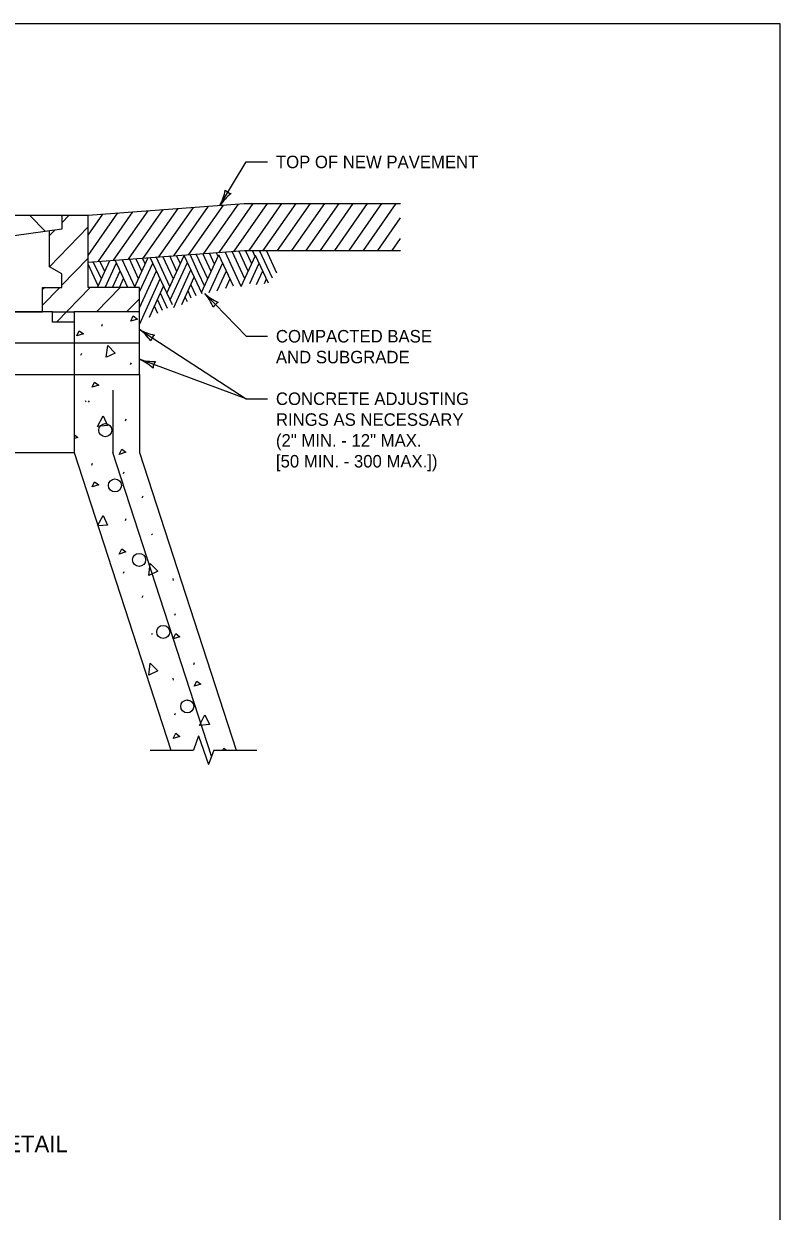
# Model space of a CAD drawing. Extents: x 49991.4 to 50021, y 49987.6 to 50011.4.
# Drawn here: x 50004.98 to 50008.61, y 50005.56 to 50011.26 of the extents above; entities that cross this region are included whole.
import ezdxf

# ---------------------------------------------------------------- set-up
doc = ezdxf.new("R2010")
doc.units = 0
for name, color, linetype in [('Level 1', 7, 'Continuous'), ('Level 2', 7, 'Continuous'), ('Level 3', 7, 'Continuous'), ('Level 4', 7, 'Continuous'), ('Level 6', 7, 'Continuous')]:
    doc.layers.add(name, color=color, linetype=linetype)

msp = doc.modelspace()

# ---------------------------------------------------------------- linework, layer by layer
at = {"layer": 'Level 1'}
for p, q in [((50005.2912, 50010.3439), (50006.0412, 50010.3995)), ((50005.4134, 50010.1279), (50005.5796, 50010.3653)), ((50005.4859, 50010.1333), (50005.6521, 50010.3707)), ((50005.5583, 50010.1387), (50005.7245, 50010.376)), ((50005.6306, 50010.144), (50005.797, 50010.3814)), ((50005.703, 50010.1494), (50005.8693, 50010.3868)), ((50005.7755, 50010.1548), (50005.9417, 50010.3921)), ((50005.848, 50010.1601), (50006.0142, 50010.3975)), ((50005.9204, 50010.1655), (50006.0842, 50010.3995)), ((50005.9928, 50010.1708), (50006.1529, 50010.3995)), ((50006.0412, 50010.3995), (50006.7912, 50010.3995)), ((50006.0641, 50010.1745), (50006.2216, 50010.3995)), ((50006.1327, 50010.1745), (50006.2902, 50010.3995)), ((50006.2014, 50010.1745), (50006.359, 50010.3995)), ((50006.2701, 50010.1745), (50006.4276, 50010.3995)), ((50006.3387, 50010.1745), (50006.4963, 50010.3995)), ((50006.4074, 50010.1745), (50006.5649, 50010.3995)), ((50006.476, 50010.1745), (50006.6336, 50010.3995)), ((50006.5447, 50010.1745), (50006.7023, 50010.3995)), ((50006.6134, 50010.1745), (50006.7709, 50010.3995)), ((50003.6589, 50010.3439), (50005.2912, 50010.3439)), ((50005.011, 50010.3439), (50005.0866, 50010.2656)), ((50005.161, 50010.3439), (50005.1661, 50010.3385)), ((50005.1661, 50010.3439), (50005.1661, 50010.2767)), ((50005.2012, 50010.3439), (50005.1661, 50010.3076)), ((50005.2912, 50010.1496), (50005.4347, 50010.3545)), ((50005.2912, 50010.2476), (50005.3622, 50010.3492)), ((50005.2912, 50009.9971), (50005.2912, 50010.3439)), ((50005.3411, 50010.1226), (50005.5071, 50010.3599)), ((50006.682, 50010.1745), (50006.7912, 50010.3304)), ((50005.1661, 50010.2767), (50004.4752, 50010.1795)), ((50005.2912, 50010.2875), (50005.107, 50010.0964)), ((50005.1316, 50010.2719), (50005.107, 50010.2464)), ((50005.107, 50010.0964), (50005.107, 50010.2684)), ((50006.7508, 50010.1745), (50006.7912, 50010.2323)), ((50005.2912, 50010.1375), (50005.1661, 50010.0076)), ((50005.2912, 50010.1189), (50006.0422, 50010.1745)), ((50005.5139, 50009.9971), (50005.5801, 50010.1403)), ((50005.5491, 50010.0749), (50005.5215, 50010.136)), ((50005.5661, 50010.11), (50005.5533, 50010.1383)), ((50005.6961, 50009.9141), (50005.5897, 50010.141)), ((50005.6848, 50010.0014), (50005.6189, 50010.1432)), ((50005.7012, 50010.0368), (50005.6511, 50010.1455)), ((50005.6701, 50009.9698), (50005.7533, 50010.1502)), ((50005.7183, 50010.0738), (50005.6843, 50010.148)), ((50005.7347, 50010.11), (50005.7162, 50010.1504)), ((50005.8385, 50009.9656), (50005.7533, 50010.1502)), ((50005.8238, 50010.0631), (50005.7816, 50010.1552)), ((50005.8661, 50010.0379), (50005.8102, 50010.1573)), ((50005.8356, 50009.972), (50005.9199, 50010.1542)), ((50005.8825, 50010.0734), (50005.843, 50010.1598)), ((50005.8991, 50010.1093), (50005.875, 50010.1621)), ((50005.9157, 50010.1451), (50005.9068, 50010.1645)), ((50005.9903, 50010.0032), (50005.9199, 50010.1543)), ((50006.0265, 50010.001), (50005.9492, 50010.1676)), ((50006.044, 50010.0391), (50005.9837, 50010.1702)), ((50006.06, 50010.0749), (50006.0156, 50010.1725)), ((50006.0266, 50010.0009), (50006.0959, 50010.1509)), ((50006.0422, 50010.1745), (50006.7912, 50010.1745)), ((50006.077, 50010.11), (50006.0476, 50010.1745)), ((50006.0936, 50010.1459), (50006.0806, 50010.1745)), ((50006.1584, 50010.0175), (50006.0959, 50010.1509)), ((50006.1768, 50010.0419), (50006.1152, 50010.1745)), ((50006.1985, 50010.066), (50006.1484, 50010.1745)), ((50005.1661, 50010.0622), (50005.107, 50010.0964)), ((50005.34, 50010.0052), (50005.2912, 50010.1095)), ((50005.3552, 50010.038), (50005.3167, 50010.1203)), ((50005.3363, 50009.9971), (50005.3963, 50010.1267)), ((50005.3716, 50010.0734), (50005.3503, 50010.1203)), ((50005.3729, 50009.9971), (50005.4276, 50010.1145)), ((50005.4823, 50009.9971), (50005.4211, 50010.1285)), ((50005.5174, 50009.9971), (50005.4554, 50010.1311)), ((50005.5331, 50010.0391), (50005.4897, 50010.1336)), ((50005.5378, 50009.9756), (50005.6021, 50010.1142)), ((50005.6855, 50009.9369), (50005.7682, 50010.1165)), ((50005.7025, 50009.9005), (50005.785, 50010.081)), ((50005.8723, 50009.9723), (50005.9385, 50010.1145)), ((50006.0674, 50010.0158), (50006.113, 50010.1141)), ((50005.1661, 50009.9971), (50005.1661, 50010.0622)), ((50005.408, 50009.9971), (50005.4451, 50010.0772)), ((50005.4426, 50009.9971), (50005.4623, 50010.0399)), ((50005.5378, 50009.8988), (50005.6196, 50010.0772)), ((50005.5378, 50009.8186), (50005.6375, 50010.0387)), ((50005.7416, 50009.9149), (50005.8014, 50010.046)), ((50005.8508, 50010.0052), (50005.8238, 50010.0631)), ((50005.9111, 50009.9804), (50005.956, 50010.0772)), ((50005.9521, 50009.9941), (50005.9731, 50010.0398)), ((50006.1001, 50010.0111), (50006.1305, 50010.0772)), ((50006.1377, 50010.0152), (50006.1484, 50010.0387)), ((50005.0734, 50009.8795), (50005.0734, 50009.9971)), ((50005.0734, 50009.9971), (50005.1661, 50009.9971)), ((50005.0836, 50009.9971), (50005.0734, 50009.9866)), ((50005.1559, 50009.9971), (50005.0734, 50009.9116)), ((50005.3008, 50009.9971), (50005.14, 50009.8306)), ((50005.5378, 50009.9971), (50005.2912, 50009.9971)), ((50005.4454, 50009.9971), (50005.332, 50009.8795)), ((50005.5378, 50009.8795), (50005.5378, 50009.9971)), ((50005.5868, 50009.8543), (50005.6544, 50010.0033)), ((50005.6733, 50009.8955), (50005.6392, 50009.9699)), ((50005.7872, 50009.9462), (50005.7715, 50009.9805)), ((50005.8103, 50009.9564), (50005.7854, 50010.0108)), ((50005.5378, 50009.9428), (50005.4766, 50009.8795)), ((50005.6494, 50009.8863), (50005.6253, 50009.9391)), ((50005.7681, 50009.9281), (50005.7578, 50009.9505)), ((50005.1202, 50009.8795), (50003.8302, 50009.8795)), ((50003.8767, 50009.8795), (50005.0734, 50009.8795)), ((50005.1202, 50009.8795), (50005.0734, 50009.8795)), ((50005.1202, 50009.8306), (50005.1202, 50009.8795)), ((50005.5378, 50009.8795), (50005.2252, 50009.8795)), ((50005.2252, 50009.8795), (50005.2252, 50009.2045)), ((50005.5378, 50009.7295), (50005.5378, 50009.8795)), ((50005.6262, 50009.8721), (50005.6105, 50009.9065)), ((50005.2252, 50009.8306), (50005.1202, 50009.8306)), ((50005.3576, 50009.8114), (50005.3615, 50009.8204)), ((50005.5378, 50009.7295), (50003.4126, 50009.7295)), ((50005.2569, 50009.6718), (50005.2608, 50009.6808)), ((50005.5378, 50009.5795), (50005.5378, 50009.7295)), ((50005.4953, 50009.6266), (50005.4995, 50009.6356)), ((50003.4126, 50009.5795), (50005.5378, 50009.5795)), ((50005.5378, 50009.5795), (50005.5378, 50009.2045)), ((50005.2768, 50009.4541), (50005.281, 50009.4481)), ((50005.2921, 50009.452), (50005.296, 50009.446)), ((50005.4106, 50009.5045), (50005.4106, 50009.2045)), ((50005.4709, 50009.3572), (50005.4748, 50009.3662)), ((50003.7252, 50009.2045), (50005.2252, 50009.2045)), ((50005.2252, 50009.2045), (50005.6896, 50007.7756)), ((50005.8843, 50007.7469), (50005.4106, 50009.2045)), ((50005.5378, 50009.2045), (50006.0019, 50007.7756)), ((50005.3092, 50009.1442), (50005.3131, 50009.1532)), ((50005.461, 50009.1034), (50005.4649, 50009.1124)), ((50005.5519, 50008.9876), (50005.5558, 50008.9966)), ((50005.4709, 50008.8787), (50005.4748, 50008.8877)), ((50005.5957, 50008.8148), (50005.5999, 50008.8088)), ((50005.461, 50008.6249), (50005.4649, 50008.6339)), ((50005.6986, 50008.6), (50005.6995, 50008.591)), ((50005.5519, 50008.5091), (50005.5558, 50008.5181)), ((50005.7667, 50008.4974), (50005.7682, 50008.4953)), ((50005.7076, 50008.4233), (50005.7118, 50008.4323)), ((50005.5957, 50008.3363), (50005.5999, 50008.3303)), ((50005.7988, 50008.1875), (50005.803, 50008.1965)), ((50005.6986, 50008.1215), (50005.6995, 50008.1125)), ((50005.7667, 50008.0189), (50005.7706, 50008.0129)), ((50005.7076, 50007.9448), (50005.7118, 50007.9538))]:
    msp.add_line(p, q, dxfattribs=at)
msp.add_lwpolyline([(50008.6146, 50011.2628), (50000.3356, 50011.2628), (50000.3356, 50000.0624), (50008.6146, 50000.0624)], close=True, dxfattribs=at)
for points in [[(50005.4966, 50009.8356), (50005.5086, 50009.8605), (50005.5287, 50009.8455), (50005.4966, 50009.8356)], [(50005.2371, 50009.7642), (50005.2491, 50009.7891), (50005.2689, 50009.7741), (50005.2371, 50009.7642)], [(50005.3784, 50009.6616), (50005.3862, 50009.7186), (50005.4219, 50009.6817), (50005.3793, 50009.6616)], [(50005.311, 50009.5177), (50005.323, 50009.5426), (50005.3431, 50009.5276), (50005.311, 50009.5177)], [(50005.3362, 50009.3302), (50005.3632, 50009.3812), (50005.3842, 50009.3341), (50005.3371, 50009.3302)], [(50005.2252, 50009.2906), (50005.2429, 50009.2771), (50005.2252, 50009.2717)], [(50005.4412, 50009.1958), (50005.4532, 50009.2207), (50005.473, 50009.2057), (50005.4412, 50009.1958)], [(50005.311, 50009.0392), (50005.323, 50009.0644), (50005.3431, 50009.0494), (50005.311, 50009.0392)], [(50005.3383, 50008.8562), (50005.3632, 50008.9027), (50005.3842, 50008.8556), (50005.3398, 50008.852)], [(50005.4412, 50008.7173), (50005.4532, 50008.7422), (50005.473, 50008.7272), (50005.4412, 50008.7173)], [(50005.5825, 50008.6147), (50005.5903, 50008.6717), (50005.626, 50008.6348), (50005.5834, 50008.615)], [(50005.7007, 50008.3105), (50005.7127, 50008.3354), (50005.7328, 50008.3204), (50005.7007, 50008.3105)], [(50005.5825, 50008.1362), (50005.5903, 50008.1932), (50005.626, 50008.1563), (50005.5834, 50008.1365)], [(50005.8009, 50008.0828), (50005.8129, 50008.1077), (50005.833, 50008.0927), (50005.8009, 50008.0828)], [(50005.8258, 50007.895), (50005.8528, 50007.946), (50005.8738, 50007.8989), (50005.827, 50007.895)], [(50005.7007, 50007.832), (50005.7127, 50007.8572), (50005.7328, 50007.8422), (50005.7007, 50007.832)], [(50005.938, 50007.7756), (50005.9428, 50007.7858), (50005.9566, 50007.7756)]]:
    msp.add_lwpolyline(points, dxfattribs=at)
for centre in [(50005.3743, 50009.3119), (50005.4205, 50009.0467), (50005.5363, 50008.6894), (50005.6521, 50008.3435), (50005.7676, 50007.9862)]:
    msp.add_circle(centre, 0.0313, dxfattribs=at)
at = {"layer": 'Level 3'}
for p, q in [((50005.9247, 50010.3909), (50006.0507, 50010.5995)), ((50006.0507, 50010.5995), (50006.1534, 50010.5995)), ((50005.8516, 50009.9682), (50006.0507, 50009.7628)), ((50005.5378, 50009.7958), (50006.0507, 50009.4628)), ((50006.0507, 50009.7628), (50006.1534, 50009.7628)), ((50006.0507, 50009.4628), (50005.5378, 50009.6521)), ((50006.0507, 50009.4628), (50006.1534, 50009.4628))]:
    msp.add_line(p, q, dxfattribs=at)
for centre, radius, start, end in [((50005.7195, 50010.5013), 0.233, 331.6942, 350.9441), ((50006.1101, 50010.2682), 0.2223, 126.3229, 146.5064), ((50005.991, 50010.5006), 0.0548, 221.0057, 256.7281), ((50005.6857, 50009.8201), 0.2223, 21.5692, 41.7527), ((50006.0107, 50010.1384), 0.233, 226.9405, 246.1904), ((50005.9408, 50009.8761), 0.0548, 116.2521, 151.9744), ((50005.4092, 50009.6145), 0.2223, 34.4624, 54.6459), ((50005.6549, 50009.9972), 0.233, 239.8337, 259.0835), ((50005.6453, 50009.726), 0.0548, 129.1452, 164.8676), ((50005.4523, 50009.4469), 0.2223, 47.198, 67.3815), ((50005.6076, 50009.8744), 0.233, 252.5693, 271.8192), ((50005.6581, 50009.6077), 0.0548, 141.8808, 177.6032)]:
    msp.add_arc(centre, radius, start, end, dxfattribs=at)
at = {"layer": 'Level 4'}
msp.add_line((50005.1202, 50009.8795), (50005.2252, 50009.8795), dxfattribs=at)
at = {"layer": 'Level 6'}
for p, q in [((50005.8216, 50007.8442), (50005.7973, 50007.7756)), ((50005.8216, 50007.8442), (50005.8459, 50007.7756)), ((50005.5896, 50007.7756), (50005.7973, 50007.7756)), ((50005.8459, 50007.7756), (50005.8702, 50007.707)), ((50005.8945, 50007.7756), (50005.8702, 50007.707)), ((50005.8942, 50007.7756), (50006.1019, 50007.7756))]:
    msp.add_line(p, q, dxfattribs=at)

# ---------------------------------------------------------------- texts
at = {"layer": 'Level 2'}
for s, height, p in [('TOP OF NEW PAVEMENT', 0.06, (50006.1934, 50010.5695)), ('COMPACTED BASE', 0.06, (50006.1934, 50009.7328)), ('AND SUBGRADE', 0.06, (50006.1934, 50009.6328)), ('CONCRETE ADJUSTING', 0.06, (50006.1934, 50009.4328)), ('RINGS AS NECESSARY', 0.06, (50006.1934, 50009.3328)), ('(2" MIN. - 12" MAX.', 0.06, (50006.1934, 50009.2328)), ('[50 MIN. - 300 MAX.])', 0.06, (50006.1934, 50009.1328)), ('MANHOLE ADJUSTMENT DETAIL', 0.08, (50003.5125, 50005.8456))]:
    msp.add_text(s, height=height, dxfattribs=at).set_placement(p)

doc.saveas('drawing.dxf')
